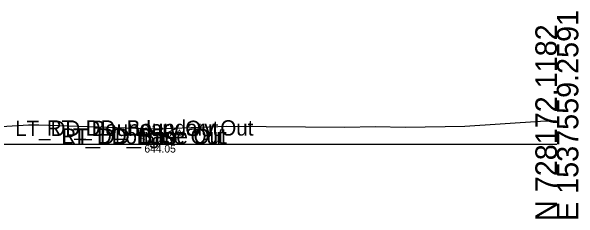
# Model space of a CAD drawing. Extents: x -26 to 1203, y -10 to 9522.
# Drawn here: x 128.9 to 202.8, y 6990.3 to 7017.3 of the extents above; entities that cross this region are included whole.
import ezdxf

# ---------------------------------------------------------------- set-up
doc = ezdxf.new("R2010")
doc.units = 0
for name, color, linetype in [('Exist Cross Section Cell', 7, 'Continuous'), ('Exist XS Ground Line', 7, 'Continuous'), ('Old_Level_63', 7, 'Continuous'), ('Prop CMT Ditch DDE', 7, 'Continuous'), ('Prop XS Ditch Slope Text', 7, 'Continuous'), ('Prop XS Ditch Standard Text', 7, 'Continuous')]:
    doc.layers.add(name, color=color, linetype=linetype)

msp = doc.modelspace()

# ---------------------------------------------------------------- linework, layer by layer
at = {"layer": 'Exist Cross Section Cell'}
msp.add_line((100, 7000), (200, 7000), dxfattribs=at)
at = {"layer": 'Exist XS Ground Line'}
msp.add_lwpolyline([(50.776, 7002.62), (63.554, 7002.008), (74.66, 7002.225), (78.297, 7002.26), (79.416, 7002.261), (86.514, 7000.947), (94.101, 7000.928), (95.234, 7001), (100, 7001.063), (115.734, 7001.269), (116.198, 7001.395), (118.503, 7001.689), (128.337, 7002.358), (131.182, 7002.531), (131.684, 7002.524), (132.519, 7002.523), (147.659, 7002.024), (157.018, 7002.342), (172.392, 7002.215), (176.324, 7002.325), (180.275, 7002.202), (188.014, 7002.358), (197.86, 7003.017), (200, 7003.055)], dxfattribs=at)
at = {"layer": 'Prop CMT Ditch DDE'}
for points in [[(148.4, 7001.05), (146.367, 7002.067)], [(148.4, 7001.05), (150.544, 7002.122)], [(148.4, 7001.05), (148.4, 7001.05)]]:
    msp.add_lwpolyline(points, dxfattribs=at)

# ---------------------------------------------------------------- texts
at = {"layer": 'Exist Cross Section Cell'}
for s, p in [('E 1537559.2591', (202.8, 6990)), ('N 728172.1182', (200, 6990))]:
    msp.add_text(s, height=2.8, rotation=90, dxfattribs=at).set_placement(p)
at = {"layer": 'Old_Level_63'}
for s, p in [('LT_DD_Boundary Out', (129.437, 7001.067)), ('RT_DD_Boundary Out', (133.568, 7001.122)), ('RT_DD_Base Out', (135.439, 7000.05)), ('LT_DD_Base Out', (135.487, 7000.05)), ('origin', (143.817, 7000.05))]:
    msp.add_text(s, height=2, dxfattribs=at).set_placement(p)
at = {"layer": 'Prop XS Ditch Slope Text'}
for rotation, p in [(333.43495, (145.409, 7000.988)), (26.56505, (149.906, 7000.34))]:
    msp.add_text('2:1', height=1, rotation=rotation, dxfattribs=at).set_placement(p)
at = {"layer": 'Prop XS Ditch Standard Text'}
msp.add_text('644.05', height=1, dxfattribs=at).set_placement((146.273, 6998.913))

doc.saveas('drawing.dxf')
